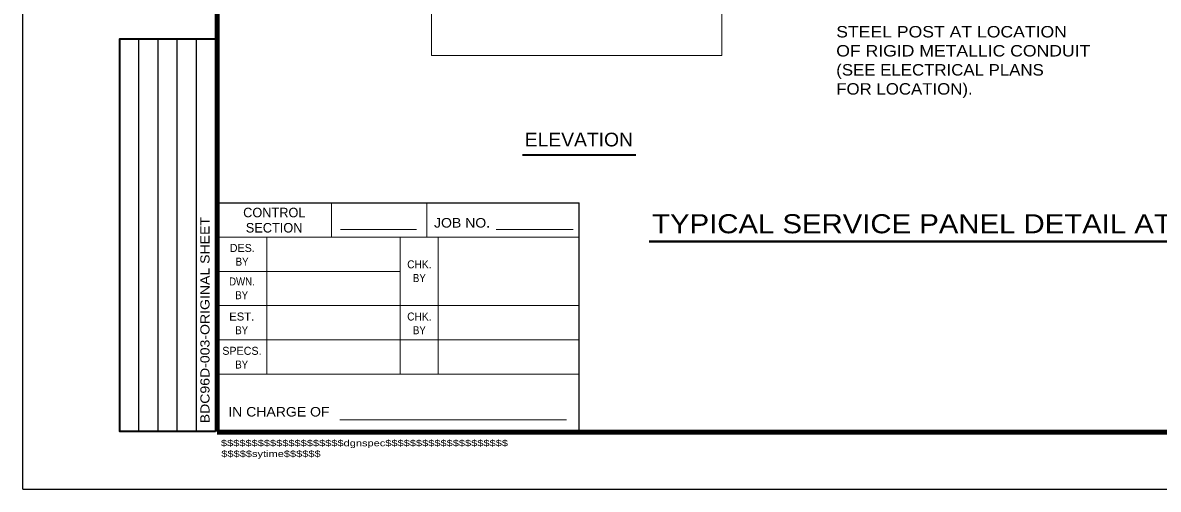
# Model space of a CAD drawing. Extents: x 312601.858 to 312602.699, y 144420.109 to 144420.704.
# Drawn here: x 312601.8578 to 312602.1557, y 144420.1095 to 144420.232 of the extents above; entities that cross this region are included whole.
import ezdxf
from ezdxf.enums import TextEntityAlignment as Align

# ---------------------------------------------------------------- set-up
doc = ezdxf.new("R2010")
doc.units = 0
doc.header["$LTSCALE"] = 0.0012
doc.linetypes.add('LONG_DASHED', pattern=[7.5, 6, -1.5])
for name, color, linetype, lineweight in [('1', 7, 'Continuous', 25), ('2', 7, 'Continuous', 25), ('39', 7, 'Continuous', 13), ('60', 7, 'Continuous', 25)]:
    doc.layers.add(name, color=color, linetype=linetype, lineweight=lineweight)

msp = doc.modelspace()

# ---------------------------------------------------------------- linework, layer by layer
at = {"layer": '1', "linetype": 'LONG_DASHED', "lineweight": 13}
msp.add_line((312601.965, 144420.2234), (312601.965, 144420.2414), dxfattribs=at)
at = {"layer": '1', "lineweight": 35}
msp.add_line((312601.9889, 144420.1973), (312602.0186, 144420.1973), dxfattribs=at)
at = {"layer": '1', "lineweight": 40}
msp.add_line((312602.0221, 144420.1745), (312602.2317, 144420.1745), dxfattribs=at)
at = {"layer": '1', "linetype": 'LONG_DASHED', "lineweight": 13}
msp.add_lwpolyline([(312601.965, 144420.2234), (312602.0412, 144420.2234), (312602.0412, 144420.2414)], dxfattribs=at)
at = {"layer": '39', "lineweight": 25}
for p, q in [((312601.8578, 144420.1095), (312601.8578, 144420.7035)), ((312601.9088, 144420.1847), (312602.0038, 144420.1847)), ((312602.0038, 144420.1247), (312602.0038, 144420.1847)), ((312601.8578, 144420.1095), (312602.6988, 144420.1095))]:
    msp.add_line(p, q, dxfattribs=at)
at = {"layer": '39', "lineweight": 158}
for p, q in [((312601.9088, 144420.1247), (312601.9088, 144420.6645)), ((312601.9088, 144420.1245), (312602.6838, 144420.1245))]:
    msp.add_line(p, q, dxfattribs=at)
at = {"layer": '39'}
for p, q in [((312601.9088, 144420.1247), (312601.9088, 144420.1847)), ((312601.9388, 144420.1757), (312601.9388, 144420.1847)), ((312601.9638, 144420.1757), (312601.9638, 144420.1847)), ((312601.9412, 144420.1777), (312601.9611, 144420.1777)), ((312601.982, 144420.1777), (312602.0022, 144420.1777)), ((312601.9088, 144420.1757), (312602.0038, 144420.1757)), ((312601.9218, 144420.1397), (312601.9218, 144420.1757)), ((312601.9568, 144420.1397), (312601.9568, 144420.1757)), ((312601.9668, 144420.1397), (312601.9668, 144420.1757)), ((312601.9088, 144420.1667), (312601.9568, 144420.1667)), ((312601.9088, 144420.1577), (312602.0038, 144420.1577)), ((312601.9088, 144420.1487), (312602.0038, 144420.1487)), ((312601.9088, 144420.1397), (312602.0038, 144420.1397)), ((312601.941, 144420.1277), (312602.0004, 144420.1277)), ((312601.9088, 144420.1247), (312602.0038, 144420.1247))]:
    msp.add_line(p, q, dxfattribs=at)
at = {"layer": '60'}
for p, q in [((312601.8883, 144420.1247), (312601.8883, 144420.2277)), ((312601.8933, 144420.1247), (312601.8933, 144420.2277)), ((312601.8983, 144420.1247), (312601.8983, 144420.2277)), ((312601.9034, 144420.1247), (312601.9034, 144420.2277))]:
    msp.add_line(p, q, dxfattribs=at)
at = {"layer": '60', "lineweight": 35}
msp.add_lwpolyline([(312601.9084, 144420.1247), (312601.8833, 144420.1247), (312601.8833, 144420.2277), (312601.9084, 144420.2277)], dxfattribs=at)

# ---------------------------------------------------------------- texts
at = {"layer": '1'}
for s, height, width, p in [('STEEL POST AT LOCATION', 0.003, 1.15, (312602.0712, 144420.2281)), ('OF RIGID METALLIC CONDUIT', 0.003, 1.15, (312602.0712, 144420.2231)), ('(SEE ELECTRICAL PLANS', 0.003, 1.1, (312602.0712, 144420.2181)), ('FOR LOCATION).', 0.003, 1.1, (312602.0712, 144420.2131)), ('ELEVATION', 0.0036, 1.05, (312601.9895, 144420.1995))]:
    msp.add_text(s, height=height, dxfattribs=dict(at, width=width)).set_placement(p)
for s, height, p in [('CONTROL', 0.0025, (312601.9238, 144420.1809)), ('SECTION', 0.0025, (312601.92375, 144420.1769)), ('DES.', 0.0021, (312601.9154, 144420.1718)), ('SPECS.', 0.0021, (312601.9153, 144420.1448))]:
    msp.add_text(s, height=height, dxfattribs=at).set_placement(p, align=Align.CENTER)
for s, height, width, p in [('JOB NO.', 0.0025, 1.1, (312601.97305, 144420.1782)), ('BY', 0.0021, 0.9, (312601.91535, 144420.1682)), ('CHK.', 0.0021, 0.95, (312601.96185, 144420.1675)), ('BY', 0.0021, 0.9, (312601.96185, 144420.1639)), ('DWN.', 0.0021, 0.9, (312601.9153, 144420.163)), ('BY', 0.0021, 0.9, (312601.91525, 144420.1594)), ('EST.', 0.0021, 1.05, (312601.91525, 144420.1538)), ('CHK.', 0.0021, 0.95, (312601.96185, 144420.1538)), ('BY', 0.0021, 0.9, (312601.91525, 144420.1502)), ('BY', 0.0021, 0.9, (312601.96185, 144420.1502)), ('BY', 0.0021, 0.9, (312601.91525, 144420.1412)), ('IN CHARGE OF', 0.0025, 1.1, (312601.925, 144420.1286))]:
    msp.add_text(s, height=height, dxfattribs=dict(at, width=width)).set_placement(p, align=Align.CENTER)
at = {"layer": '2', "width": 1.15}
msp.add_text('BDC96D-003-ORIGINAL SHEET', height=0.0024, rotation=90, dxfattribs=at).set_placement((312601.9068, 144420.1539), align=Align.CENTER)
msp.add_text('TYPICAL SERVICE PANEL DETAIL AT SIGN STRUCTURE', height=0.005, dxfattribs=at).set_placement((312602.1263, 144420.1767), align=Align.CENTER)
at = {"layer": '2', "width": 1.3}
for s, p in [('$$$$$$$$$$$$$$$$$$$$dgnspec$$$$$$$$$$$$$$$$$$$$', (312601.9098, 144420.1208)), ('$$$$$sytime$$$$$$', (312601.9099, 144420.118))]:
    msp.add_text(s, height=0.001664, dxfattribs=at).set_placement(p)

doc.saveas('drawing.dxf')
